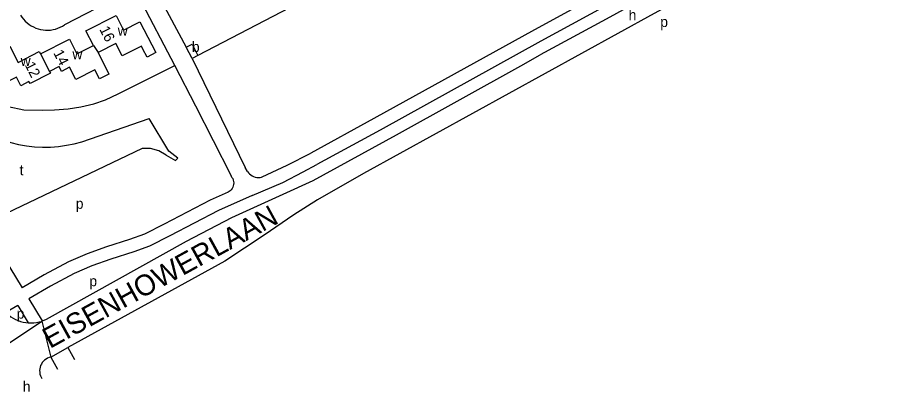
# Model space of a CAD drawing. Extents: x 162427 to 165104, y 384242 to 386287.
# Drawn here: x 163720.2 to 164052.6, y 384706.5 to 384850.5 of the extents above; entities that cross this region are included whole.
import ezdxf

# ---------------------------------------------------------------- set-up
doc = ezdxf.new("R2010")
doc.units = 0
for name, color, linetype in [('BLT_Basislijn', 7, 'Continuous'), ('BLT_Bebouwing', 7, 'Continuous'), ('BLT_Centroide', 7, 'Continuous'), ('BLT_Huisnummer', 7, 'Continuous'), ('BLT_Huisnummer_ tussenligend', 7, 'Continuous'), ('BLT_Onderverdeling_panden', 7, 'Continuous'), ('BLT_Straatnaam_hoofdweg', 7, 'Continuous'), ('BLT_Vlakafsluiter', 7, 'Continuous')]:
    doc.layers.add(name, color=color, linetype=linetype)

msp = doc.modelspace()

# ---------------------------------------------------------------- linework, layer by layer
at = {"layer": 'BLT_Basislijn'}
for p, q in [((164000.1, 384889.99), (163919.34, 384845.68)), ((163999.78, 384883.99), (163921.76, 384841.31)), ((163769.63, 384868.03), (163785.28, 384838.98)), ((163762.01, 384859.89), (163738.35, 384847.59)), ((163780.9, 384832.02), (163765.09, 384862.08)), ((163787.57, 384834.68), (163807.99, 384792.7)), ((163802.5, 384789.68), (163788.91, 384816.37)), ((163745, 384802.64), (163770.93, 384811.6)), ((163778.53, 384799.05), (163770.93, 384811.6)), ((163768.27, 384799.98), (163715.99, 384775.02)), ((163777.51, 384797.42), (163781.16, 384795.43)), ((163782.03, 384796.33), (163778.53, 384799.05)), ((163782.03, 384796.33), (163781.16, 384795.43)), ((163808.81, 384791.24), (163807.99, 384792.7)), ((163802.85, 384788.94), (163802.5, 384789.68)), ((163801.34, 384783.19), (163794.46, 384780.11)), ((163810.67, 384781.93), (163797.66, 384776.13)), ((163704.09, 384775.97), (163722.07, 384746.45)), ((163720.36, 384739.65), (163715.82, 384736.99)), ((163720.36, 384739.65), (163724.42, 384732.98)), ((163724.67, 384742.18), (163729.84, 384733.7)), ((163724.42, 384732.98), (163724.52, 384732.97)), ((163729.66, 384733.58), (163729.84, 384733.7)), ((163733.09, 384719.81), (163739.63, 384723.45)), ((163739.63, 384723.45), (163742.21, 384718.8)), ((163733.09, 384719.81), (163735.74, 384715.09))]:
    msp.add_line(p, q, dxfattribs=at)
for points in [[(164052.57, 384898.66), (164017.86, 384880.8), (163997.33, 384869.41), (163965.35, 384851.94), (163909.44, 384821.18)], [(163876.1, 384880.9), (163789.76, 384835.8)], [(164000, 384879.09), (163946.83, 384849.82), (163921.52, 384836.03)], [(163655.02, 384875.1), (163656.82, 384875.74), (163682.02, 384844.18), (163685.23, 384845.12), (163708.81, 384822.49), (163711.21, 384820.11), (163716.64, 384816.24), (163722.73, 384814.86), (163729.83, 384814.83), (163734.58, 384814.89), (163739.86, 384815.36), (163744.65, 384816.02), (163749.74, 384817.26), (163754.17, 384818.73), (163759.07, 384821.05), (163780.9, 384832.02)], [(163721.48, 384851.37), (163722.01, 384850.55), (163722.6, 384849.78), (163723.26, 384849.06), (163723.98, 384848.4), (163724.74, 384847.79), (163725.56, 384847.26), (163726.41, 384846.79), (163727.3, 384846.39), (163728.22, 384846.07), (163729.17, 384845.82), (163730.12, 384845.65), (163731.1, 384845.56), (163732.07, 384845.55), (163733.04, 384845.62), (163734.01, 384845.78), (163734.96, 384846), (163735.88, 384846.31), (163736.78, 384846.69), (163737.64, 384847.14), (163738.35, 384847.59)], [(163919.34, 384845.68), (163857.47, 384811.52), (163833.15, 384798.22)], [(163921.76, 384841.31), (163859.89, 384807.14), (163835.55, 384793.83)], [(163822.58, 384782.43), (163834.11, 384787.67), (163866.22, 384805.36), (163914.06, 384831.81), (163921.52, 384836.03)], [(163788.91, 384816.37), (163780.9, 384832.02)], [(163909.44, 384821.18), (163853.53, 384790.43), (163835.79, 384780.31)], [(163703.89, 384808.7), (163706.43, 384807.13), (163709.09, 384805.7), (163711.86, 384804.42), (163714.73, 384803.32), (163717.69, 384802.39), (163720.7, 384801.64), (163723.77, 384801.09), (163726.86, 384800.73), (163729.96, 384800.58), (163733.06, 384800.61), (163736.13, 384800.85), (163739.15, 384801.27), (163742.11, 384801.87), (163745, 384802.64)], [(163777.51, 384797.42), (163774.72, 384799.09), (163771.52, 384799.98), (163768.27, 384799.98)], [(163814.48, 384789.13), (163824.05, 384793.67), (163833.15, 384798.22)], [(163810.67, 384781.93), (163822.43, 384787.02), (163830.21, 384791.07), (163835.55, 384793.83)], [(163808.81, 384791.24), (163809.17, 384790.72), (163809.6, 384790.26), (163810.08, 384789.86), (163810.6, 384789.52), (163811.17, 384789.25), (163811.77, 384789.05), (163812.38, 384788.94), (163813.01, 384788.9), (163813.64, 384788.94), (163814.25, 384789.06), (163814.48, 384789.13)], [(163802.85, 384788.94), (163803.12, 384788.45), (163803.33, 384787.92), (163803.46, 384787.37), (163803.51, 384786.81), (163803.48, 384786.25), (163803.37, 384785.69), (163803.18, 384785.16), (163802.92, 384784.66), (163802.6, 384784.2), (163802.21, 384783.79), (163801.76, 384783.44), (163801.34, 384783.19)], [(163794.46, 384780.11), (163776.7, 384770.95), (163769.12, 384767.06), (163763.46, 384765.05), (163754.59, 384762.22), (163747.12, 384759.54), (163739.98, 384756.45), (163730.6, 384751.47), (163722.07, 384746.45)], [(163731.44, 384734.38), (163785.39, 384764.39), (163802.74, 384773.45), (163822.58, 384782.43)], [(163835.79, 384780.31), (163826.6, 384774.52), (163815.21, 384766.7), (163800.04, 384756.65), (163739.63, 384723.45)], [(163797.66, 384776.13), (163778.99, 384766.5), (163771.1, 384762.46), (163765.06, 384760.32), (163756.2, 384757.49), (163748.96, 384754.89), (163742.15, 384751.94), (163733.04, 384747.1), (163724.67, 384742.18)], [(163715.82, 384736.99), (163716.15, 384736.64), (163716.93, 384735.96), (163717.76, 384735.33), (163718.63, 384734.78), (163719.55, 384734.29), (163720.49, 384733.87), (163721.47, 384733.53), (163722.47, 384733.27), (163723.49, 384733.08), (163724.42, 384732.98)], [(163724.52, 384732.97), (163725.56, 384732.94), (163726.59, 384732.99), (163727.62, 384733.12), (163728.63, 384733.33), (163729.52, 384733.54)], [(163729.52, 384733.54), (163729.66, 384733.58)], [(163729.84, 384733.7), (163730.6, 384733.99), (163731.44, 384734.38)], [(163733.09, 384719.81), (163732.45, 384719.63), (163731.84, 384719.37), (163731.27, 384719.04), (163730.74, 384718.65), (163730.26, 384718.19), (163729.84, 384717.68), (163729.49, 384717.12), (163729.2, 384716.52), (163728.99, 384715.89), (163728.86, 384715.24), (163728.8, 384714.59), (163728.83, 384713.93), (163728.94, 384713.27), (163729.12, 384712.64), (163729.38, 384712.03), (163729.63, 384711.59)]]:
    msp.add_lwpolyline(points, dxfattribs=at)
at = {"layer": 'BLT_Bebouwing'}
for p, q in [((163767.44, 384848.83), (163771.97, 384839.98)), ((163787.57, 384834.68), (163785.28, 384838.98)), ((163789.76, 384835.8), (163787.57, 384834.68))]:
    msp.add_line(p, q, dxfattribs=at)
for points in [[(163749.51, 384839.69), (163746.63, 384845.3), (163758.23, 384851.24), (163761.12, 384845.6), (163767.44, 384848.83)], [(163717.32, 384839.44), (163720.53, 384833.19), (163728.68, 384837.37), (163729.17, 384836.42)], [(163729.17, 384836.42), (163740.29, 384842.12), (163743.19, 384836.45), (163749.51, 384839.69)], [(163771.97, 384839.98), (163773.52, 384836.95), (163770.15, 384835.22), (163768.6, 384838.25), (163767.98, 384839.44), (163760.59, 384835.65), (163758.14, 384840.43), (163751.3, 384836.93)], [(163785.28, 384838.98), (163787.52, 384840.14), (163789.76, 384835.8)], [(163732.59, 384829.7), (163732.95, 384829.01), (163725.12, 384825), (163724.71, 384825.78), (163721.62, 384824.2), (163719.91, 384827.55), (163714.98, 384825.02), (163711.13, 384832.52), (163710.12, 384832), (163708.35, 384835.47), (163713.27, 384837.99)], [(163751.3, 384836.93), (163755.51, 384828.7), (163751.88, 384826.84), (163750.1, 384830.32), (163742.79, 384826.57), (163740.36, 384831.31), (163737.24, 384829.71), (163736.28, 384831.59), (163732.59, 384829.7)]]:
    msp.add_lwpolyline(points, dxfattribs=at)
at = {"layer": 'BLT_Onderverdeling_panden'}
for p, q in [((163749.51, 384839.69), (163751.3, 384836.93)), ((163729.17, 384836.42), (163732.59, 384829.7))]:
    msp.add_line(p, q, dxfattribs=at)
at = {"layer": 'BLT_Vlakafsluiter'}
for p, q in [((163715.76, 384724.42), (163729.52, 384733.54)), ((163715.79, 384724.38), (163729.66, 384733.58)), ((163729.66, 384733.58), (163733.09, 384719.81))]:
    msp.add_line(p, q, dxfattribs=at)

# ---------------------------------------------------------------- texts
at = {"layer": 'BLT_Centroide'}
for s, p in [('h', (163955.53, 384849.41)), ('p', (163967.7, 384846.77)), ('w', (163758.88, 384843.44)), ('b', (163787.41, 384837.16)), ('w', (163741.43, 384834.34)), ('w', (163721.5, 384831.81)), ('t', (163721.1, 384789.75)), ('p', (163742.71, 384776.84)), ('p', (163747.95, 384747.05)), ('p', (163719.98, 384734.57)), ('h', (163722.33, 384706.46))]:
    msp.add_text(s, height=4, dxfattribs=at).set_placement(p)
at = {"layer": 'BLT_Huisnummer'}
for s, rotation, p in [('16', 297.1341, (163751.71, 384845.93)), ('12', 297.1339, (163723, 384832.21))]:
    msp.add_text(s, height=4, rotation=rotation, dxfattribs=at).set_placement(p)
at = {"layer": 'BLT_Huisnummer_ tussenligend'}
msp.add_text('14', height=4, rotation=297.1327, dxfattribs=at).set_placement((163733.98, 384836.84))
at = {"layer": 'BLT_Straatnaam_hoofdweg'}
msp.add_text('EISENHOWERLAAN', height=8, rotation=28.7966, dxfattribs=at).set_placement((163732.77, 384722.88))

doc.saveas('drawing.dxf')
